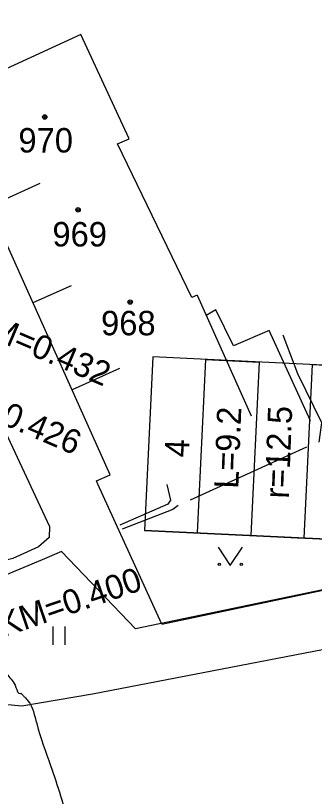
# Model space of a CAD drawing. Extents: x -478102 to -473059, y -1117705 to -1114104.
# Drawn here: x -476485.8 to -476461.4, y -1116863.1 to -1116799.2 of the extents above; entities that cross this region are included whole.
import ezdxf

# ---------------------------------------------------------------- set-up
doc = ezdxf.new("R2010")
doc.units = 0
for name, color, linetype in [('Budovy', 7, 'Continuous'), ('LokalizacniPopisyPopisnaCisla', 7, 'Continuous'), ('ObPÚ', 7, 'Continuous'), ('OstatniRozhrani', 7, 'Continuous'), ('Ploty', 7, 'Continuous'), ('POLYGONY_SITUACE_PF_POPISY', 7, 'Continuous'), ('PopisnaZnackaVyhybka', 7, 'Continuous'), ('PopisneZnackyKultura', 7, 'Continuous'), ('ramecek', 7, 'Continuous'), ('RozhraniKultur', 7, 'Continuous'), ('RozhraniVozovky', 7, 'Continuous'), ('TABULKY', 7, 'Continuous'), ('Teren_HranaSvahu', 7, 'Continuous'), ('Teren_PataSvahu', 7, 'Continuous'), ('Vrstevnice_hlavni', 7, 'Continuous'), ('Vrstevnice_vedlejsi', 7, 'Continuous'), ('Vrstva 36', 7, 'Continuous')]:
    doc.layers.add(name, color=color, linetype=linetype)

msp = doc.modelspace()

# ---------------------------------------------------------------- linework, layer by layer
at = {"layer": 'Budovy'}
for p, q in [((-476480.507, -1116800.783), (-476492.94, -1116806.52)), ((-476476.546, -1116809.326), (-476480.507, -1116800.783)), ((-476478.1, -1116836.8), (-476491.78, -1116806.38)), ((-476477.506, -1116809.723), (-476476.546, -1116809.326)), ((-476471.43, -1116822.291), (-476477.506, -1116809.723)), ((-476483.847, -1116812.976), (-476487.978, -1116814.834)), ((-476481.306, -1116821.349), (-476484.419, -1116822.749)), ((-476470.993, -1116822.098), (-476471.43, -1116822.291)), ((-476470.993, -1116822.098), (-476466.58, -1116831.98)), ((-476477.345, -1116828.114), (-476481.222, -1116829.858)), ((-476479.21, -1116837.29), (-476478.1, -1116836.8)), ((-476479.12, -1116837.58), (-476479.21, -1116837.29))]:
    msp.add_line(p, q, dxfattribs=at)
at = {"layer": 'ObPÚ'}
msp.add_lwpolyline([(-476357.4, -1116837.74), (-476422.93, -1116845.91), (-476427.37, -1116819.37), (-476430.29, -1116820.37), (-476436.91, -1116823.52), (-476455.71, -1116831.67), (-476450.1, -1116844.01), (-476476.04, -1116849.41), (-476482.1, -1116843.09), (-476483.67, -1116843.77), (-476488.84, -1116845.93), (-476490.13, -1116842.91), (-476508.98, -1116798.77)], dxfattribs=at)
at = {"layer": 'OstatniRozhrani'}
msp.add_lwpolyline([(-476461.707, -1116832.388), (-476465.092, -1116824.994), (-476468.006, -1116826.249), (-476469.449, -1116823.315), (-476470.246, -1116823.772)], dxfattribs=at)
at = {"layer": 'Ploty'}
for points in [[(-476473.88, -1116849.03), (-476479.12, -1116837.58)], [(-476473.88, -1116849.03), (-476450.1, -1116844.01)]]:
    msp.add_lwpolyline(points, dxfattribs=at)
at = {"layer": 'PopisnaZnackaVyhybka'}
for centre, radius in [((-476483.459, -1116807.534), 0.18), ((-476483.459, -1116807.534), 0.0797), ((-476480.728, -1116815.128), 0.18), ((-476480.728, -1116815.128), 0.0797), ((-476476.468, -1116822.675), 0.18), ((-476476.468, -1116822.675), 0.0797)]:
    msp.add_circle(centre, radius, dxfattribs=at)
at = {"layer": 'PopisneZnackyKultura'}
for p, q in [((-476482.773, -1116850.729), (-476482.773, -1116849.229)), ((-476481.773, -1116850.729), (-476481.773, -1116849.229))]:
    msp.add_line(p, q, dxfattribs=at)
at = {"layer": 'ramecek'}
msp.add_lwpolyline([(-476474.604, -1116827.164), (-476475.297, -1116841.353), (-476453.542, -1116842.399), (-476452.86, -1116828.21)], close=True, dxfattribs=at)
at = {"layer": 'RozhraniKultur'}
for p, q in [((-476454.277, -1116849.877), (-476479.541, -1116854.75)), ((-476479.541, -1116854.75), (-476485.323, -1116855.734)), ((-476485.323, -1116855.734), (-476488.011, -1116855.464))]:
    msp.add_line(p, q, dxfattribs=at)
at = {"layer": 'RozhraniVozovky'}
msp.add_lwpolyline([(-476490.349, -1116825.506), (-476486.291, -1116834.14), (-476483.076, -1116841.048), (-476483.085, -1116841.925), (-476483.97, -1116842.691), (-476486.077, -1116843.648), (-476487.217, -1116843.934), (-476487.93, -1116843.214), (-476491.436, -1116836.397), (-476497.994, -1116822.204), (-476502.044, -1116811.617), (-476503.151, -1116808.629), (-476503.828, -1116804.26), (-476503.771, -1116799.56), (-476501.723, -1116794.622), (-476498.437, -1116790.602), (-476493.387, -1116786.282), (-476488.978, -1116781.97)], dxfattribs=at)
at = {"layer": 'TABULKY'}
msp.add_lwpolyline([(-476453.542, -1116842.399), (-476475.297, -1116841.353), (-476470.95, -1116841.562), (-476470.267, -1116827.373), (-476465.901, -1116827.583), (-476466.583, -1116841.772), (-476462.236, -1116841.981), (-476461.554, -1116827.792), (-476457.207, -1116828.001), (-476457.889, -1116842.19), (-476453.542, -1116842.399), (-476452.86, -1116828.21), (-476474.604, -1116827.164), (-476475.297, -1116841.353)], dxfattribs=at)
at = {"layer": 'Teren_HranaSvahu'}
msp.add_lwpolyline([(-476473.464, -1116837.594), (-476473.163, -1116838.875), (-476473.383, -1116839.212), (-476477.313, -1116840.929)], dxfattribs=at)
at = {"layer": 'Teren_PataSvahu'}
msp.add_line((-476471.522, -1116838.85), (-476462.015, -1116834.526), dxfattribs=at)
for points in [[(-476460.999, -1116834.138), (-476460.776, -1116832.542), (-476462.745, -1116828.534), (-476463.949, -1116825.387)], [(-476472.538, -1116839.319), (-476472.989, -1116839.652), (-476477.134, -1116841.25)]]:
    msp.add_lwpolyline(points, dxfattribs=at)
at = {"layer": 'Vrstevnice_hlavni'}
msp.add_spline([(-476493.715, -1116836.779), (-476493.657, -1116837.782), (-476493.454, -1116838.814), (-476493.106, -1116839.874), (-476492.613, -1116840.964), (-476491.914, -1116842.563), (-476491.008, -1116844.672), (-476489.895, -1116847.291), (-476489.121, -1116849.068), (-476488.687, -1116850.006), (-476488.591, -1116850.102), (-476488.194, -1116850.666), (-476487.494, -1116851.699), (-476486.491, -1116853.199), (-476485.812, -1116854.196), (-476485.456, -1116854.691), (-476485.422, -1116854.683), (-476485.307, -1116854.78), (-476485.109, -1116854.984), (-476484.829, -1116855.293), (-476484.118, -1116857.163), (-476482.975, -1116860.594), (-476481.402, -1116865.585), (-476480.12, -1116869.665), (-476479.13, -1116872.833), (-476478.431, -1116875.088), (-476477.86, -1116876.887), (-476477.416, -1116878.229), (-476477.099, -1116879.115), (-476476.855, -1116880.078), (-476476.685, -1116881.12), (-476476.587, -1116882.239), (-476476.21, -1116884.112), (-476475.555, -1116886.737), (-476474.62, -1116890.115), (-476473.657, -1116893.01), (-476472.666, -1116895.422), (-476471.647, -1116897.352), (-476470.243, -1116900.412), (-476468.455, -1116904.603), (-476466.283, -1116909.925), (-476464.77, -1116913.634), (-476463.916, -1116915.731), (-476463.721, -1116916.214), (-476463.617, -1116916.722), (-476463.603, -1116917.256), (-476463.679, -1116917.815), (-476463.509, -1116918.911), (-476463.093, -1116920.547), (-476462.43, -1116922.72), (-476462.028, -1116926.548), (-476461.886, -1116932.03), (-476462.123, -1116946.304)], degree=3, dxfattribs=at)
at = {"layer": 'Vrstevnice_vedlejsi'}
msp.add_spline([(-476452.85, -1116834.766), (-476452.763, -1116836.45), (-476452.562, -1116837.981), (-476452.248, -1116839.358), (-476451.821, -1116840.582), (-476451.441, -1116841.599), (-476451.108, -1116842.409), (-476450.824, -1116843.01), (-476450.631, -1116843.458), (-476450.53, -1116843.75), (-476450.521, -1116843.889), (-476450.642, -1116844.019), (-476450.893, -1116844.142), (-476451.274, -1116844.257), (-476451.636, -1116844.362), (-476451.98, -1116844.456), (-476452.305, -1116844.54), (-476452.489, -1116844.891), (-476452.534, -1116845.508), (-476452.439, -1116846.393), (-476452.377, -1116847.124), (-476452.349, -1116847.701), (-476452.354, -1116848.126), (-476452.334, -1116848.53), (-476452.288, -1116848.914), (-476452.216, -1116849.278), (-476451.375, -1116851.721), (-476449.763, -1116856.244), (-476447.382, -1116862.847), (-476445.375, -1116868.421), (-476443.743, -1116872.966), (-476442.485, -1116876.483), (-476441.641, -1116878.888), (-476441.211, -1116880.182), (-476441.195, -1116880.364), (-476441.153, -1116880.565), (-476441.084, -1116880.785), (-476440.99, -1116881.025), (-476440.244, -1116882.086), (-476438.849, -1116883.967), (-476436.803, -1116886.669), (-476434.982, -1116889.477), (-476433.386, -1116892.391), (-476432.015, -1116895.411), (-476430.876, -1116899.416), (-476429.969, -1116904.405), (-476429.293, -1116910.379), (-476428.831, -1116914.444), (-476428.585, -1116916.601), (-476428.553, -1116916.85), (-476428.523, -1116917.047), (-476428.494, -1116917.192), (-476428.467, -1116917.285), (-476428.451, -1116917.352), (-476428.447, -1116917.391), (-476428.453, -1116917.404), (-476428.455, -1116917.446), (-476428.452, -1116917.518), (-476428.446, -1116917.62), (-476428.12, -1116922.385), (-476427.475, -1116931.814), (-476426.511, -1116945.907), (-476425.976, -1116956.8), (-476425.87, -1116964.494), (-476426.194, -1116968.988), (-476426.432, -1116974.931), (-476426.584, -1116982.322), (-476426.65, -1116991.161), (-476427.252, -1117000.578), (-476428.388, -1117010.572), (-476430.059, -1117021.144), (-476430.881, -1117029.111), (-476430.854, -1117034.474), (-476429.978, -1117037.232), (-476429.977, -1117042.889), (-476430.852, -1117051.444), (-476432.602, -1117062.898), (-476433.9, -1117071.162), (-476434.745, -1117076.235), (-476435.138, -1117078.117), (-476435.697, -1117079.572), (-476436.421, -1117080.6), (-476437.311, -1117081.2), (-476438.104, -1117081.861), (-476438.8, -1117082.583), (-476439.4, -1117083.366), (-476442.225, -1117086.66), (-476447.274, -1117092.463), (-476454.548, -1117100.776), (-476460.096, -1117107.53), (-476463.917, -1117112.726), (-476466.012, -1117116.363), (-476467.87, -1117119.015), (-476469.493, -1117120.681), (-476470.879, -1117121.362), (-476472.889, -1117123.083), (-476475.524, -1117125.843)], degree=3, dxfattribs=at)
at = {"layer": 'Vrstva 36'}
msp.add_lwpolyline([(-476469.278, -1116842.726), (-476468.278, -1116844.226), (-476467.278, -1116842.726)], dxfattribs=at)
for centre in [(-476469.178, -1116844.126), (-476467.379, -1116844.126)]:
    msp.add_circle(centre, 0.1, dxfattribs=at)

# ---------------------------------------------------------------- texts
for s, height, p in [('L=9.2', 1.9765, (-476467.622, -1116837.97)), ('r=12.5', 1.9765, (-476463.492, -1116838.773)), ('4', 1.976, (-476471.675, -1116835.402))]:
    msp.add_text(s, height=height, rotation=87.82518).set_placement(p)
at = {"layer": 'LokalizacniPopisyPopisnaCisla'}
for s, p in [('970', (-476485.61, -1116810.44)), ('969', (-476482.83, -1116818.126)), ('968', (-476478.849, -1116825.395))]:
    msp.add_text(s, height=2, dxfattribs=at).set_placement(p)
at = {"layer": 'POLYGONY_SITUACE_PF_POPISY'}
for s, rotation, p in [('KM=0.432', 336.82626, (-476489.763, -1116824.827)), ('KM=0.426', 336.82626, (-476492.169, -1116830.446)), ('KM=0.400', 18.82411, (-476486.827, -1116850.104))]:
    msp.add_text(s, height=1.9765, rotation=rotation, dxfattribs=at).set_placement(p)

doc.saveas('drawing.dxf')
